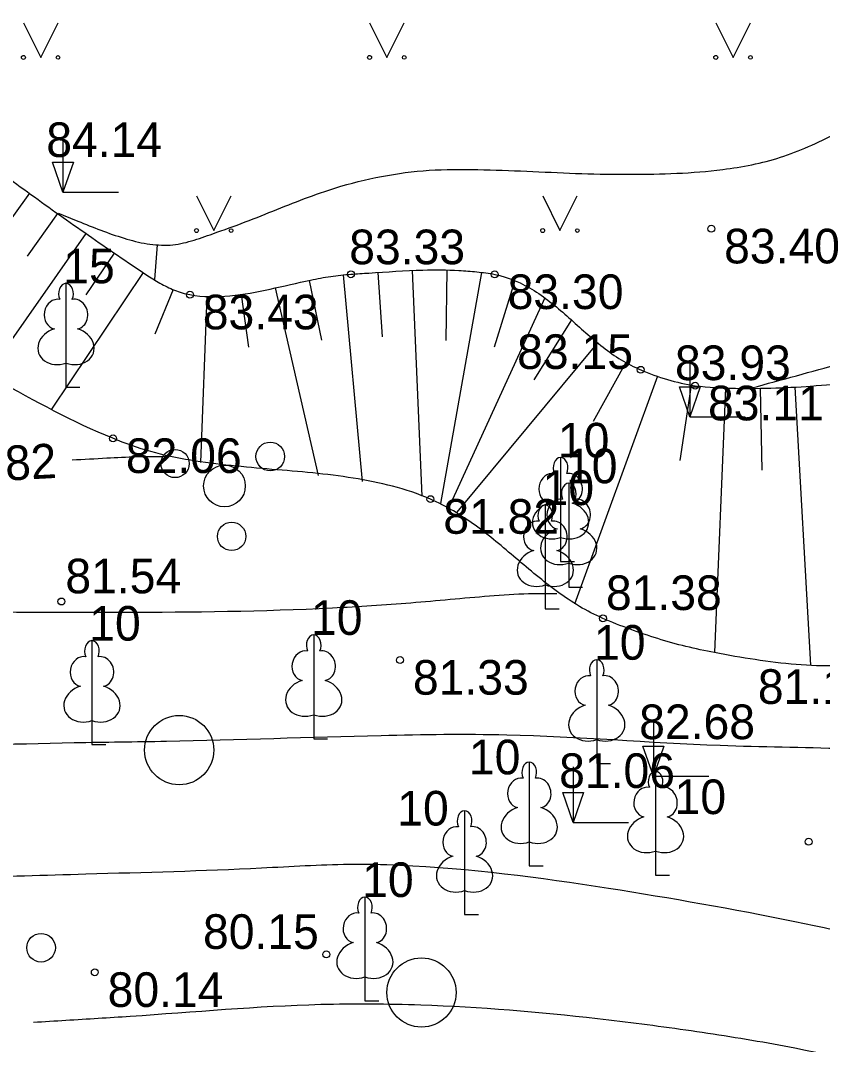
# Model space of a CAD drawing. Extents: x 576692 to 577659, y 273254 to 273799.
# Drawn here: x 577207.21 to 577218.79, y 273433.25 to 273448.03 of the extents above; entities that cross this region are included whole.
import ezdxf

# ---------------------------------------------------------------- set-up
doc = ezdxf.new("R2010")
doc.units = 0
for name, color, linetype in [('APGR_SARK_####_####_#', 7, 'Continuous'), ('DREN_VADP_####_####_#', 7, 'Continuous'), ('GAZE_ELEM_####_####_#', 7, 'Continuous'), ('GEOD_ELEM_####_TKST_#', 7, 'Continuous'), ('GEOD_SITP_####_TKST_#', 7, 'Continuous'), ('HIDT_REZV_####_TKST_#', 7, 'Continuous'), ('LKAN_ELEM_PAST_TKST_#', 7, 'Continuous'), ('RELJ_ELEM_####_####_#', 7, 'Continuous'), ('RELJ_HORZ_PAMT_####_#', 7, 'Continuous'), ('SAKT_ELEM_####_####_#', 7, 'Continuous')]:
    doc.layers.add(name, color=color, linetype=linetype)

msp = doc.modelspace()

# ---------------------------------------------------------------- linework, layer by layer
at = {"layer": 'DREN_VADP_####_####_#'}
msp.add_spline([(577252.982, 273414.853), (577251.974, 273414.319), (577251.296, 273413.895), (577249.566, 273411.91), (577248.903, 273411.509), (577248.444, 273411.498), (577247.696, 273411.504), (577246.444, 273411.535), (577244.846, 273411.363), (577244.022, 273411.247), (577241.708, 273410.879), (577240.339, 273410.502), (577239, 273410.046), (577237.665, 273409.574), (577236.308, 273409.148), (577232.395, 273408.229), (577230.233, 273408.289), (577228.16, 273408.614), (577226.772, 273408.795), (577225.035, 273408.894), (577216.714, 273409.044), (577215.802, 273409.128), (577214.183, 273409.253), (577210.948, 273409.331), (577207.808, 273409.112), (577206.24, 273408.92), (577204.358, 273408.692), (577200.757, 273408.499), (577197.064, 273408.225), (577195.293, 273408.274), (577193.884, 273408.307), (577192.404, 273408.351), (577191.034, 273408.298), (577188.672, 273408.17), (577187.769, 273408), (577187.12, 273407.732), (577186.576, 273407.527), (577186.03, 273407.46), (577185.261, 273408.176), (577184.947, 273408.486), (577184.626, 273408.818), (577184.295, 273409.183), (577183.826, 273409.606), (577182.671, 273410.193), (577181.38, 273410.806), (577180.079, 273411.403), (577178.701, 273412.153), (577176.151, 273413.713), (577175.37, 273414.363), (577174.894, 273414.947), (577174.466, 273415.545), (577174.114, 273416.004), (577171.235, 273418.393), (577170.422, 273418.755), (577169.358, 273419.229), (577168.284, 273419.699), (577167.376, 273420.223), (577166.523, 273421.019), (577166.325, 273421.442), (577166.264, 273421.836), (577166.208, 273422.249), (577166.113, 273422.474), (577165.735, 273422.577), (577165.493, 273422.415), (577164.833, 273422.237), (577164.536, 273422.311), (577162.044, 273423.335), (577157.906, 273424.803), (577155.548, 273425.078), (577154.221, 273424.995), (577152.73, 273424.792), (577149.601, 273423.667), (577149.132, 273423.331), (577148.389, 273422.813), (577147.644, 273422.309), (577147.083, 273422.041), (577145.741, 273421.593), (577144.586, 273421.422), (577143.433, 273421.242), (577142.637, 273421.093), (577137.334, 273418.585), (577135.002, 273417.571), (577133.759, 273417.478), (577132.689, 273417.77), (577131.611, 273418.15), (577130.554, 273418.322), (577129.877, 273418.108), (577129.214, 273417.682), (577128.473, 273417.311), (577127.7, 273417.376), (577125.9, 273418.627), (577123.805, 273421.904), (577122.752, 273424.503), (577122.635, 273425.088), (577122.595, 273425.692), (577122.541, 273426.294), (577122.379, 273426.874), (577120.633, 273429.122), (577118.876, 273430.502), (577117.365, 273431.308), (577114.934, 273432.161), (577112.354, 273432.529), (577111.381, 273432.669), (577110.378, 273432.861), (577108.182, 273433.552), (577106.895, 273434.234)], degree=3, dxfattribs=at)
at = {"layer": 'GAZE_ELEM_####_####_#'}
for p, q in [((577207.337, 273445.538), (577205.839, 273443.46)), ((577207.743, 273445.247), (577207.303, 273444.63)), ((577208.152, 273444.958), (577206.726, 273442.925)), ((577208.563, 273444.674), (577208.153, 273444.07)), ((577208.978, 273444.395), (577207.657, 273442.42)), ((577212.368, 273444.396), (577212.43, 273443.465)), ((577212.867, 273444.425), (577213.006, 273441.167)), ((577213.866, 273444.396), (577213.274, 273441.061)), ((577213.367, 273444.432), (577213.352, 273443.415)), ((577211.376, 273444.281), (577211.556, 273443.418)), ((577211.87, 273444.361), (577212.144, 273441.379)), ((577214.35, 273444.28), (577214.05, 273443.319)), ((577209.412, 273444.148), (577209.147, 273443.506)), ((577210.888, 273444.171), (577211.507, 273441.466)), ((577209.899, 273444.049), (577209.807, 273441.652)), ((577210.397, 273444.077), (577210.503, 273443.316)), ((577214.781, 273444.028), (577213.393, 273441.002)), ((577215.165, 273443.709), (577214.624, 273442.844)), ((577215.543, 273443.381), (577213.509, 273440.935)), ((577215.951, 273443.094), (577215.478, 273442.243)), ((577216.41, 273442.896), (577215.209, 273439.607)), ((577216.893, 273442.769), (577216.729, 273441.681)), ((577217.391, 273442.728), (577217.233, 273438.907)), ((577217.891, 273442.722), (577217.915, 273441.539)), ((577218.39, 273442.741), (577218.62, 273438.727))]:
    msp.add_line(p, q, dxfattribs=at)
msp.add_spline([(577202.087, 273445.896), (577202.403, 273446.118), (577202.789, 273446.352), (577202.991, 273446.455), (577203.196, 273446.557), (577203.556, 273446.717), (577203.924, 273446.851), (577204.297, 273446.965), (577204.672, 273447.063), (577205.114, 273447.054), (577205.491, 273446.841), (577206.33, 273446.262), (577207.153, 273445.671), (577207.978, 273445.08), (577208.821, 273444.5), (577209.222, 273444.242), (577209.432, 273444.139), (577209.542, 273444.101), (577209.655, 273444.075), (577210.233, 273444.058), (577210.814, 273444.155), (577211.397, 273444.285), (577211.688, 273444.338), (577211.98, 273444.37), (577212.239, 273444.387), (577213.02, 273444.43), (577213.541, 273444.425), (577213.8, 273444.404), (577214.058, 273444.367), (577214.627, 273444.133), (577215.129, 273443.741), (577215.622, 273443.317), (577215.884, 273443.134), (577216.166, 273442.99), (577216.952, 273442.761), (577217.534, 273442.723), (577218.117, 273442.728), (577219.287, 273442.812), (577220.456, 273442.904), (577221.621, 273442.892), (577222.244, 273442.828), (577222.862, 273442.736), (577224.088, 273442.418), (577224.315, 273442.331)], degree=3, dxfattribs=at)
at = {"layer": 'GEOD_ELEM_####_TKST_#'}
for points in [[(577207.953, 273441.691), (577208.454, 273441.717), (577208.884, 273441.737), (577209.351, 273441.737)], [(577207.394, 273433.571), (577208.332, 273433.63), (577208.793, 273433.659), (577211.547, 273433.83), (577212.991, 273433.822), (577215.544, 273433.625), (577216.816, 273433.461), (577218.086, 273433.258), (577220.498, 273432.651), (577221.969, 273432.083), (577223.036, 273431.687), (577223.31, 273431.604)]]:
    msp.add_spline(points, degree=3, dxfattribs=at)
at = {"layer": 'GEOD_SITP_####_TKST_#'}
msp.add_line((577209.15, 273444.294), (577209.188, 273444.793), dxfattribs=at)
for points in [[(577207.753, 273445.249), (577208.036, 273445.136), (577208.703, 273444.89), (577209.037, 273444.81), (577209.203, 273444.792), (577209.37, 273444.791), (577209.678, 273444.851), (577209.986, 273444.954), (577210.454, 273445.124), (577210.911, 273445.305), (577211.368, 273445.482), (577211.837, 273445.639), (577213.195, 273445.875), (577213.901, 273445.878), (577214.608, 273445.853), (577215.314, 273445.823), (577216.021, 273445.813), (577217.35, 273445.882), (577218.184, 273446.058), (577218.588, 273446.212), (577218.987, 273446.405), (577219.398, 273446.692), (577219.724, 273447.075), (577220.003, 273447.589), (577220.185, 273448.135), (577220.387, 273449.67), (577220.243, 273450.776), (577220.053, 273451.877), (577219.951, 273452.335), (577219.95, 273452.341)], [(577217.772, 273442.729), (577219.059, 273443.083), (577220.336, 273443.475), (577220.386, 273443.493), (577221.564, 273444.167), (577222.162, 273444.596), (577222.413, 273444.853), (577222.514, 273445.001), (577222.596, 273445.165), (577222.747, 273445.719), (577222.801, 273446.285), (577222.814, 273446.57), (577222.827, 273446.855), (577222.893, 273447.417)], [(577192.223, 273441.82), (577192.669, 273441.655), (577193.966, 273441.277), (577196.519, 273440.627), (577197.136, 273440.508), (577203.987, 273439.696), (577204.891, 273439.619), (577205.795, 273439.551), (577207.605, 273439.489), (577207.813, 273439.49), (577207.915, 273439.491), (577208.686, 273439.492), (577211.713, 273439.554), (577212.846, 273439.628), (577213.981, 273439.726), (577214.547, 273439.759), (577214.83, 273439.762), (577214.953, 273439.763)], [(577226.069, 273437.986), (577226.063, 273437.986), (577225.667, 273437.912), (577225.279, 273437.784), (577224.89, 273437.646), (577224.494, 273437.542), (577222.728, 273437.316), (577220.467, 273437.448), (577219.105, 273437.519), (577217.314, 273437.564), (577214.232, 273437.717), (577212.416, 273437.708), (577209.316, 273437.624), (577207.983, 273437.603), (577205.222, 273437.569), (577203.626, 273437.65), (577200.779, 273437.897), (577196.026, 273438.267), (577194.73, 273438.423), (577192.798, 273438.717), (577191.841, 273438.921), (577190.892, 273439.188), (577190.408, 273439.416), (577189.951, 273439.696), (577189.597, 273439.951), (577189.252, 273440.216)], [(577229.528, 273434.696), (577228.811, 273434.44), (577228.093, 273434.163), (577227.077, 273433.74), (577226.625, 273433.614), (577225.865, 273433.58), (577224.619, 273433.686), (577222.91, 273433.78), (577222.886, 273433.785), (577222.863, 273433.793), (577222.831, 273433.805), (577218.391, 273435.021), (577215.702, 273435.502), (577212.683, 273435.835), (577211.95, 273435.848), (577210.689, 273435.795), (577208.153, 273435.708), (577204.598, 273435.61), (577203.143, 273435.592), (577196.078, 273435.666), (577195.486, 273435.681), (577195.463, 273435.683), (577195.34, 273435.701), (577194.109, 273435.908), (577192.883, 273436.138), (577191.66, 273436.393), (577190.441, 273436.675), (577188.159, 273437.582), (577187.574, 273437.944), (577187.005, 273438.321), (577186.056, 273439.02)]]:
    msp.add_spline(points, degree=3, dxfattribs=at)
at = {"layer": 'LKAN_ELEM_PAST_TKST_#'}
for p, q in [((577207.25, 273448), (577207.5, 273447.5)), ((577207.5, 273447.5), (577207.75, 273448)), ((577212.25, 273448), (577212.5, 273447.5)), ((577212.5, 273447.5), (577212.75, 273448)), ((577217.25, 273448), (577217.5, 273447.5)), ((577217.5, 273447.5), (577217.75, 273448)), ((577207.821, 273446.354), (577207.821, 273445.554)), ((577207.821, 273445.554), (577208.621, 273445.554)), ((577209.75, 273445.5), (577210, 273445)), ((577210, 273445), (577210.25, 273445.5)), ((577214.75, 273445.5), (577215, 273445)), ((577215, 273445), (577215.25, 273445.5)), ((577207.865, 273443.086), (577207.865, 273442.739)), ((577216.876, 273443.113), (577216.876, 273442.313)), ((577207.865, 273442.739), (577208.065, 273442.739)), ((577216.876, 273442.313), (577217.676, 273442.313)), ((577215.009, 273440.571), (577215.009, 273440.224)), ((577215.009, 273440.224), (577215.209, 273440.224)), ((577215.126, 273440.199), (577215.126, 273439.852)), ((577214.788, 273439.884), (577214.788, 273439.537)), ((577215.126, 273439.852), (577215.326, 273439.852)), ((577214.788, 273439.537), (577214.988, 273439.537)), ((577208.24, 273437.927), (577208.24, 273437.58)), ((577211.443, 273438.01), (577211.443, 273437.663)), ((577216.349, 273437.924), (577216.349, 273437.124)), ((577211.443, 273437.663), (577211.643, 273437.663)), ((577215.531, 273437.652), (577215.531, 273437.305)), ((577208.24, 273437.58), (577208.44, 273437.58)), ((577215.531, 273437.305), (577215.731, 273437.305)), ((577215.189, 273437.257), (577215.189, 273436.457)), ((577216.349, 273437.124), (577217.149, 273437.124)), ((577215.189, 273436.457), (577215.989, 273436.457)), ((577214.556, 273436.174), (577214.556, 273435.827)), ((577216.38, 273436.041), (577216.38, 273435.694)), ((577214.556, 273435.827), (577214.756, 273435.827)), ((577216.38, 273435.694), (577216.58, 273435.694)), ((577213.622, 273435.472), (577213.622, 273435.125)), ((577213.622, 273435.125), (577213.822, 273435.125)), ((577212.182, 273434.226), (577212.182, 273433.879)), ((577212.182, 273433.879), (577212.382, 273433.879))]:
    msp.add_line(p, q, dxfattribs=at)
for points in [[(577207.865, 273444.239), (577207.865, 273443.086)], [(577207.955, 273444.007), (577207.954, 273444.008)], [(577215.009, 273441.724), (577215.009, 273440.571)], [(577215.099, 273441.492), (577215.098, 273441.493)], [(577215.126, 273441.352), (577215.126, 273440.199)], [(577214.788, 273441.037), (577214.788, 273439.884)], [(577215.216, 273441.12), (577215.215, 273441.121)], [(577214.878, 273440.805), (577214.877, 273440.806)], [(577208.24, 273439.08), (577208.24, 273437.927)], [(577211.443, 273439.163), (577211.443, 273438.01)], [(577211.533, 273438.931), (577211.532, 273438.932)], [(577208.33, 273438.848), (577208.329, 273438.849)], [(577215.531, 273438.805), (577215.531, 273437.652)], [(577215.621, 273438.573), (577215.62, 273438.574)], [(577214.556, 273437.327), (577214.556, 273436.174)], [(577216.38, 273437.194), (577216.38, 273436.041)], [(577214.646, 273437.095), (577214.645, 273437.096)], [(577216.47, 273436.962), (577216.469, 273436.963)], [(577213.622, 273436.625), (577213.622, 273435.472)], [(577213.712, 273436.393), (577213.711, 273436.394)], [(577212.182, 273435.379), (577212.182, 273434.226)], [(577212.272, 273435.147), (577212.271, 273435.148)]]:
    msp.add_lwpolyline(points, dxfattribs=at)
for centre, radius in [((577207.25, 273447.5), 0.028), ((577207.75, 273447.5), 0.0263), ((577212.25, 273447.5), 0.028), ((577212.75, 273447.5), 0.0263), ((577217.25, 273447.5), 0.028), ((577217.75, 273447.5), 0.0263), ((577209.75, 273445), 0.028), ((577210.25, 273445), 0.0263), ((577214.75, 273445), 0.028), ((577215.25, 273445), 0.0263), ((577210.815, 273441.738), 0.207), ((577209.44, 273441.637), 0.204), ((577210.154, 273441.313), 0.301), ((577210.257, 273440.585), 0.205), ((577209.5, 273437.5), 0.5), ((577207.505, 273434.647), 0.207), ((577213, 273434), 0.5)]:
    msp.add_circle(centre, radius, dxfattribs=at)
for centre, major_axis, ratio, start_param, end_param in [((577207.865, 273444.089), (0, -0.15), 0.707107, 3.14537, 5.287485), ((577207.865, 273444.089), (0, -0.15), 0.707107, 0.995701, 3.137816), ((577207.737, 273443.794), (-0.039, -0.212), 0.861323, 3.141593, 6.283185), ((577207.993, 273443.794), (0.039, -0.212), 0.861323, 0, 3.141593), ((577207.775, 273443.332), (0.307, 0.095), 0.814445, 1.570796, 4.752015), ((577207.955, 273443.332), (-0.307, 0.095), 0.814445, 1.531171, 4.712389), ((577215.009, 273441.574), (0, -0.15), 0.707107, 3.14537, 5.287485), ((577215.009, 273441.574), (0, -0.15), 0.707107, 0.995701, 3.137816), ((577214.881, 273441.279), (-0.039, -0.212), 0.861323, 3.141593, 6.283185), ((577215.137, 273441.279), (0.039, -0.212), 0.861323, 0, 3.141593), ((577215.126, 273441.202), (0, -0.15), 0.707107, 3.14537, 5.287485), ((577215.126, 273441.202), (0, -0.15), 0.707107, 0.995701, 3.137816), ((577214.919, 273440.817), (0.307, 0.095), 0.814445, 1.570796, 4.752015), ((577214.788, 273440.887), (0, -0.15), 0.707107, 3.14537, 5.287485), ((577214.788, 273440.887), (0, -0.15), 0.707107, 0.995701, 3.137816), ((577214.998, 273440.907), (-0.039, -0.212), 0.861323, 3.141593, 6.283185), ((577215.099, 273440.817), (-0.307, 0.095), 0.814445, 1.531171, 4.712389), ((577215.254, 273440.907), (0.039, -0.212), 0.861323, 0, 3.141593), ((577214.66, 273440.592), (-0.039, -0.212), 0.861323, 3.141593, 6.283185), ((577214.916, 273440.592), (0.039, -0.212), 0.861323, 0, 3.141593), ((577215.036, 273440.445), (0.307, 0.095), 0.814445, 1.570796, 4.752015), ((577215.216, 273440.445), (-0.307, 0.095), 0.814445, 1.531171, 4.712389), ((577214.698, 273440.13), (0.307, 0.095), 0.814445, 1.570796, 4.752015), ((577214.878, 273440.13), (-0.307, 0.095), 0.814445, 1.531171, 4.712389), ((577208.24, 273438.93), (0, -0.15), 0.707107, 3.14537, 5.287485), ((577208.24, 273438.93), (0, -0.15), 0.707107, 0.995701, 3.137816), ((577211.443, 273439.013), (0, -0.15), 0.707107, 3.14537, 5.287485), ((577211.443, 273439.013), (0, -0.15), 0.707107, 0.995701, 3.137816), ((577211.315, 273438.718), (-0.039, -0.212), 0.861323, 3.141593, 6.283185), ((577211.571, 273438.718), (0.039, -0.212), 0.861323, 0, 3.141593), ((577208.112, 273438.635), (-0.039, -0.212), 0.861323, 3.141593, 6.283185), ((577208.368, 273438.635), (0.039, -0.212), 0.861323, 0, 3.141593), ((577215.531, 273438.655), (0, -0.15), 0.707107, 3.14537, 5.287485), ((577215.531, 273438.655), (0, -0.15), 0.707107, 0.995701, 3.137816), ((577211.353, 273438.256), (0.307, 0.095), 0.814445, 1.570796, 4.752015), ((577211.533, 273438.256), (-0.307, 0.095), 0.814445, 1.531171, 4.712389), ((577215.403, 273438.36), (-0.039, -0.212), 0.861323, 3.141593, 6.283185), ((577215.659, 273438.36), (0.039, -0.212), 0.861323, 0, 3.141593), ((577208.15, 273438.173), (0.307, 0.095), 0.814445, 1.570796, 4.752015), ((577208.33, 273438.173), (-0.307, 0.095), 0.814445, 1.531171, 4.712389), ((577215.441, 273437.898), (0.307, 0.095), 0.814445, 1.570796, 4.752015), ((577215.621, 273437.898), (-0.307, 0.095), 0.814445, 1.531171, 4.712389), ((577214.556, 273437.177), (0, -0.15), 0.707107, 3.14537, 5.287485), ((577214.556, 273437.177), (0, -0.15), 0.707107, 0.995701, 3.137816), ((577216.38, 273437.044), (0, -0.15), 0.707107, 3.14537, 5.287485), ((577216.38, 273437.044), (0, -0.15), 0.707107, 0.995701, 3.137816), ((577214.428, 273436.882), (-0.039, -0.212), 0.861323, 3.141593, 6.283185), ((577214.684, 273436.882), (0.039, -0.212), 0.861323, 0, 3.141593), ((577216.252, 273436.749), (-0.039, -0.212), 0.861323, 3.141593, 6.283185), ((577216.508, 273436.749), (0.039, -0.212), 0.861323, 0, 3.141593), ((577213.622, 273436.475), (0, -0.15), 0.707107, 3.14537, 5.287485), ((577213.622, 273436.475), (0, -0.15), 0.707107, 0.995701, 3.137816), ((577214.466, 273436.42), (0.307, 0.095), 0.814445, 1.570796, 4.752015), ((577214.646, 273436.42), (-0.307, 0.095), 0.814445, 1.531171, 4.712389), ((577213.494, 273436.18), (-0.039, -0.212), 0.861323, 3.141593, 6.283185), ((577213.75, 273436.18), (0.039, -0.212), 0.861323, 0, 3.141593), ((577216.29, 273436.287), (0.307, 0.095), 0.814445, 1.570796, 4.752015), ((577216.47, 273436.287), (-0.307, 0.095), 0.814445, 1.531171, 4.712389), ((577213.532, 273435.718), (0.307, 0.095), 0.814445, 1.570796, 4.752015), ((577213.712, 273435.718), (-0.307, 0.095), 0.814445, 1.531171, 4.712389), ((577212.182, 273435.229), (0, -0.15), 0.707107, 3.14537, 5.287485), ((577212.182, 273435.229), (0, -0.15), 0.707107, 0.995701, 3.137816), ((577212.054, 273434.934), (-0.039, -0.212), 0.861323, 3.141593, 6.283185), ((577212.31, 273434.934), (0.039, -0.212), 0.861323, 0, 3.141593), ((577212.092, 273434.472), (0.307, 0.095), 0.814445, 1.570796, 4.752015), ((577212.272, 273434.472), (-0.307, 0.095), 0.814445, 1.531171, 4.712389)]:
    msp.add_ellipse(centre, major_axis=major_axis, ratio=ratio, start_param=start_param, end_param=end_param, dxfattribs=at)
at = {"layer": 'RELJ_ELEM_####_####_#'}
for points in [[(577207.671, 273445.987), (577207.971, 273445.987), (577207.821, 273445.554)], [(577216.726, 273442.746), (577217.026, 273442.746), (577216.876, 273442.313)], [(577216.199, 273437.557), (577216.499, 273437.557), (577216.349, 273437.124)], [(577215.039, 273436.89), (577215.339, 273436.89), (577215.189, 273436.457)]]:
    msp.add_lwpolyline(points, close=True, dxfattribs=at)
for centre in [(577217.185, 273445.026), (577211.98, 273444.37), (577214.058, 273444.367), (577209.655, 273444.074), (577216.166, 273442.99), (577216.952, 273442.76), (577208.544, 273442), (577213.129, 273441.123), (577207.799, 273439.645), (577215.62, 273439.402), (577212.69, 273438.8), (577218.591, 273436.177), (577211.624, 273434.55), (577208.281, 273434.292)]:
    msp.add_circle(centre, 0.05, dxfattribs=at)
at = {"layer": 'SAKT_ELEM_####_####_#'}
msp.add_spline([(577223.214, 273439.569), (577222.921, 273439.623), (577222.773, 273439.638), (577222.625, 273439.645), (577222.284, 273439.615), (577221.946, 273439.53), (577221.215, 273439.283), (577220.591, 273439.042), (577220.092, 273438.882), (577219.838, 273438.82), (577219.583, 273438.77), (577219.001, 273438.716), (577218.411, 273438.735), (577217.82, 273438.806), (577217.233, 273438.907), (577216.819, 273438.996), (577216.413, 273439.109), (577216.013, 273439.245), (577215.619, 273439.402), (577215.281, 273439.575), (577214.964, 273439.786), (577214.367, 273440.267), (577213.773, 273440.746), (577213.128, 273441.123), (577212.583, 273441.308), (577212.014, 273441.426), (577210.839, 273441.553), (577209.662, 273441.685), (577209.091, 273441.809), (577208.543, 273442.001), (577206.872, 273442.841), (577205.277, 273443.824), (577204.757, 273444.241), (577204.276, 273444.711), (577203.784, 273445.163), (577203.519, 273445.361), (577203.233, 273445.529), (577203.049, 273445.593), (577202.856, 273445.629), (577202.662, 273445.663), (577202.476, 273445.722), (577202.087, 273445.896)], degree=3, dxfattribs=at)

# ---------------------------------------------------------------- texts
at = {"layer": 'APGR_SARK_####_####_#'}
for s, p in [(' 15', (577207.64, 273444.239)), (' 10', (577214.784, 273441.724)), (' 10', (577214.901, 273441.352)), (' 10', (577214.563, 273441.037)), (' 10', (577211.218, 273439.163)), (' 10', (577208.015, 273439.08)), (' 10', (577215.306, 273438.805)), (' 10', (577213.499, 273437.15)), (' 10', (577216.47, 273436.576)), (' 10', (577212.464, 273436.411)), (' 10', (577211.957, 273435.379))]:
    msp.add_text(s, height=0.5, dxfattribs=at).set_placement(p)
at = {"layer": 'HIDT_REZV_####_TKST_#'}
for s, p in [(' 84.14', (577207.395, 273446.062)), (' 83.33', (577211.77, 273444.514)), (' 83.40', (577217.185, 273444.526)), (' 83.30', (577214.058, 273443.867)), (' 83.43', (577209.655, 273443.574)), (' 83.15', (577214.195, 273443.002)), (' 83.93', (577216.475, 273442.841)), (' 83.11', (577216.952, 273442.26)), (' 82.06', (577208.544, 273441.5)), (' 81.82', (577213.129, 273440.623)), (' 81.54', (577207.67, 273439.763)), (' 81.38', (577215.478, 273439.522)), (' 81.33', (577212.69, 273438.3)), (' 81.18', (577217.672, 273438.167)), (' 82.68', (577215.958, 273437.658)), (' 81.06', (577214.802, 273436.953)), (' 80.15', (577209.658, 273434.63)), (' 80.14', (577208.281, 273433.792))]:
    msp.add_text(s, height=0.5, dxfattribs=at).set_placement(p)
at = {"layer": 'RELJ_HORZ_PAMT_####_#'}
msp.add_text('82', height=0.5, rotation=3.0777, dxfattribs=at).set_placement((577206.997, 273441.39))

doc.saveas('drawing.dxf')
